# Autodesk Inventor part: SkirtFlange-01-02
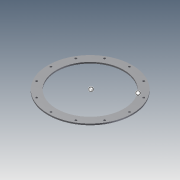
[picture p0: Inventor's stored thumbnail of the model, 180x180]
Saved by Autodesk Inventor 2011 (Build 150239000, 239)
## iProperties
Created: 2010-06
Part Number: SkirtFlange-01-02
Document SubType Name: Modeling
Designer: mklassen
Density: 1 g/cm^3
OD: 36.000 in
THK: 0.625 in
WDT: 3.000 in
BHN: 24.000 ul
BHD: 0.750 in
BCD: 20.125 in
Author: mklassen
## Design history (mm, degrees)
sketch "skSkirtFlange"
  geometry: C1 r 457.2 at (0, 0); C2 r 533.4 at (0, 0); 1 further point
  constraints: 2 centre point, 2 coincident
  dimensions: "d0" = 76.2 radial gap between concentric circles of C2 C1 (derived); "d1" = 914.4 diameter of C1 (derived)
extrude "SkirtFlange" new body sketch "skSkirtFlange" stored distance "d2" = 15.875 (derived); taper "d3" = 0 deg
sketch "skBoltHole"
  geometry: C1 r 457.2 at (0, 0) reference; 2 further points
  constraints: 1 coincident, 1 vertical alignment
  dimensions: "d7" = 511.175 distance of point (0, 511.175) point (0, 0) (= BCD)
hole "BoltHole" sketch "skBoltHole" at (0, 511.175) diameter "d8" = 19.05 (derived); stored, may be unused: countersink angle "d12" = 82 deg, drill point angle "d14" = 118 deg; dims "d9" = 19.05, "d10" = 9.525, "d11" = 6.35, "d13" = 25.4
body "Solid1"
pattern_circular "BoltCircle" dims angle "d16" = 360 deg
other parameters: "BCD" = 511.175 [user parameter; used in 2 equation terms], "d4" = 0, "d5" = 0, "d6" = 0
